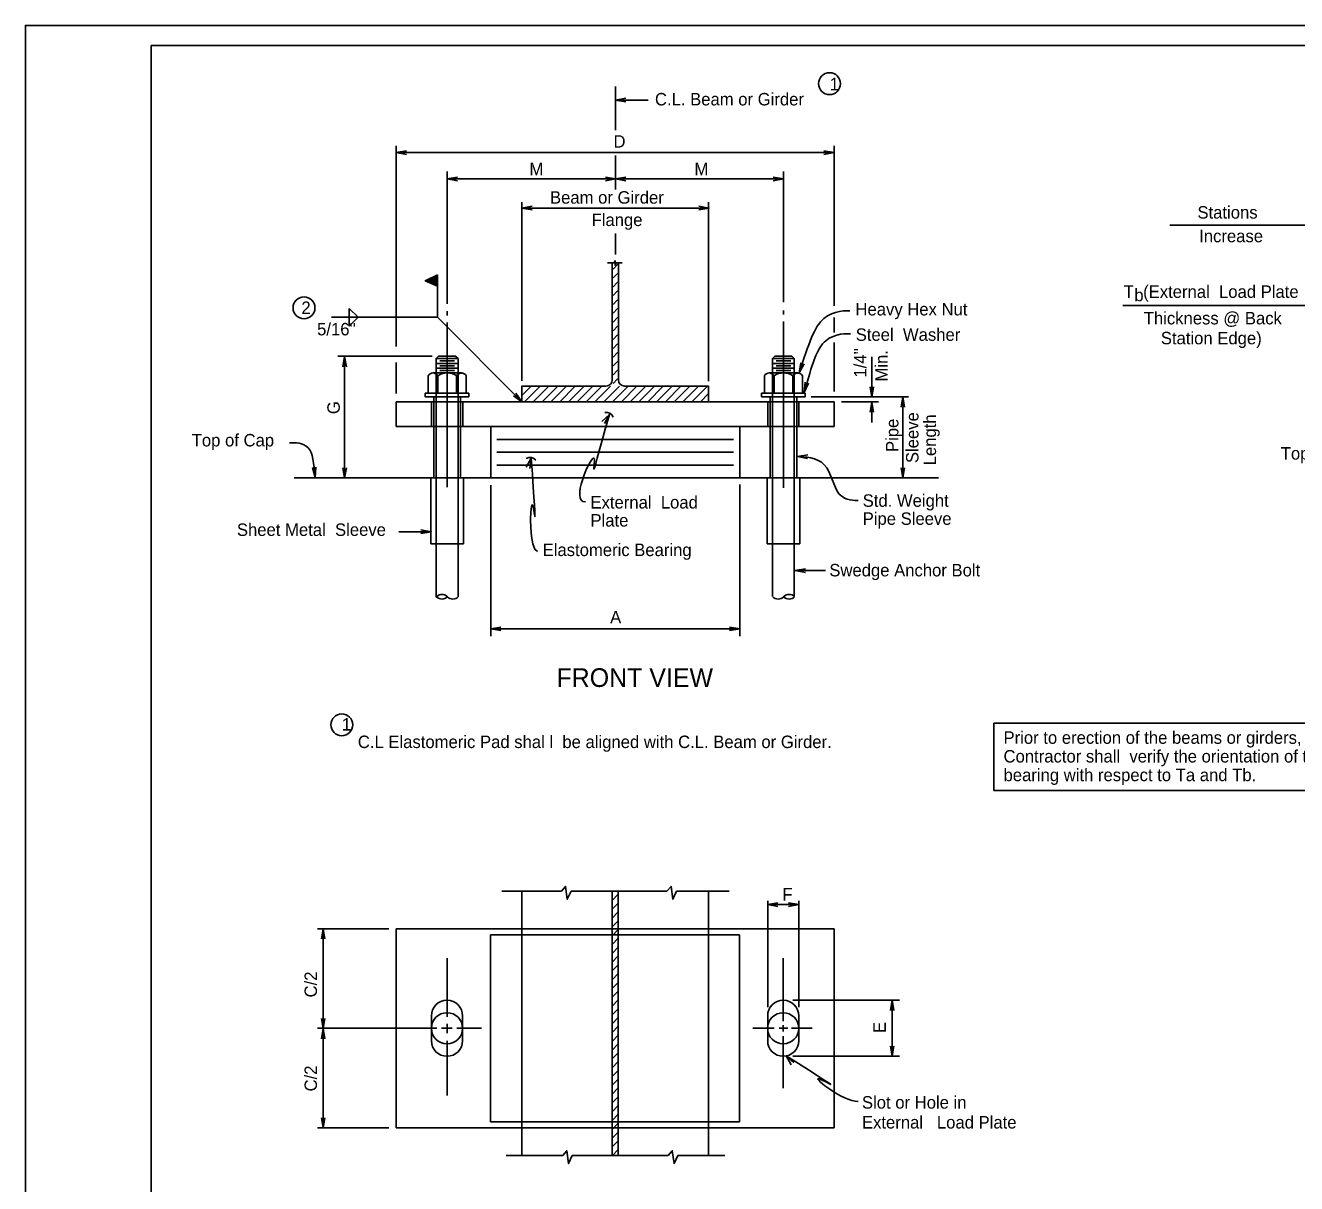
# Model space of a CAD drawing. Extents: x 32334 to 32601, y -901 to -733.
# Drawn here: x 32334.2 to 32436.3, y -826 to -733 of the extents above; entities that cross this region are included whole.
import ezdxf

# ---------------------------------------------------------------- set-up
doc = ezdxf.new("R2010")
doc.units = 0
for name, color, linetype in [('1', 7, 'Continuous'), ('B_Dimension', 7, 'Continuous'), ('Level 1', 7, 'Continuous'), ('Level 63', 7, 'Continuous')]:
    doc.layers.add(name, color=color, linetype=linetype)

msp = doc.modelspace()

# ---------------------------------------------------------------- linework, layer by layer
at = {"layer": '1'}
for p, q in [((32381.6, -741.38), (32381.6, -737.87)), ((32381.6, -738.97), (32384.21, -738.97)), ((32363.99, -758.76), (32363.99, -742.65)), ((32399.15, -755.49), (32399.15, -742.65)), ((32363.99, -743.19), (32399.15, -743.19)), ((32381.6, -746.15), (32381.6, -743.43)), ((32368.07, -755.33), (32368.07, -744.72)), ((32395.07, -755.2), (32395.07, -744.71)), ((32368.07, -745.31), (32381.6, -745.31)), ((32381.6, -745.31), (32395.07, -745.31)), ((32374.07, -761.51), (32374.07, -747.17)), ((32389.07, -761.54), (32389.07, -747.17)), ((32374.07, -747.64), (32389.09, -747.64)), ((32426.1, -749.02), (32438.8, -749.02)), ((32381.6, -751.38), (32381.6, -749.7)), ((32380.95, -752.04), (32381.48, -752.04)), ((32381.32, -752.04), (32381.32, -761.45)), ((32381.48, -752.04), (32381.57, -751.87)), ((32381.57, -751.87), (32381.57, -752.26)), ((32381.57, -752.26), (32381.64, -752.04)), ((32381.64, -752.04), (32382.13, -752.04)), ((32381.82, -761.45), (32381.82, -752.04)), ((32367.29, -753.02), (32366.31, -753.48)), ((32367.29, -753.93), (32367.29, -753.02)), ((32367.29, -753.02), (32367.29, -753.02)), ((32366.31, -753.48), (32367.29, -753.93)), ((32367.29, -753.93), (32367.29, -754.3)), ((32367.29, -754.3), (32367.29, -756.41)), ((32360.21, -757.12), (32360.21, -755.7)), ((32360.21, -755.7), (32360.92, -756.41)), ((32368.07, -756.27), (32368.07, -755.94)), ((32395.07, -756.19), (32395.07, -755.86)), ((32422.32, -755.47), (32439.1, -755.47)), ((32367.29, -756.41), (32358.78, -756.41)), ((32360.92, -756.41), (32360.21, -757.12)), ((32374.07, -763.2), (32367.29, -756.41)), ((32368.07, -770.06), (32368.07, -756.84)), ((32395.07, -770.12), (32395.07, -756.75)), ((32399.15, -757.63), (32399.15, -756.43)), ((32399.15, -762.39), (32399.15, -758.45)), ((32366.87, -759.53), (32359.29, -759.53)), ((32359.84, -769.32), (32359.84, -759.58)), ((32363.99, -762.53), (32363.99, -760.06)), ((32367.39, -759.53), (32367.2, -759.73)), ((32367.2, -760.89), (32367.2, -759.73)), ((32367.2, -759.73), (32368.95, -759.73)), ((32367.2, -760.12), (32368.95, -760.12)), ((32367.39, -759.53), (32368.75, -759.53)), ((32367.49, -759.92), (32368.66, -759.92)), ((32367.49, -760.31), (32368.66, -760.31)), ((32368.75, -759.53), (32368.95, -759.73)), ((32368.95, -760.89), (32368.95, -759.73)), ((32394.2, -759.73), (32394.39, -759.53)), ((32394.2, -759.73), (32395.95, -759.73)), ((32394.2, -760.89), (32394.2, -759.73)), ((32394.2, -759.73), (32395.95, -759.73)), ((32394.2, -760.12), (32395.95, -760.12)), ((32394.39, -759.53), (32395.75, -759.53)), ((32394.49, -759.92), (32395.66, -759.92)), ((32394.49, -760.31), (32395.66, -760.31)), ((32395.75, -759.53), (32395.95, -759.73)), ((32395.95, -760.89), (32395.95, -759.73)), ((32402.17, -762.83), (32402.17, -759.6)), ((32366.55, -762.5), (32366.55, -761.11)), ((32366.93, -760.89), (32369.22, -760.89)), ((32367.2, -760.51), (32368.95, -760.51)), ((32367.2, -769.32), (32367.2, -760.89)), ((32367.32, -762.5), (32367.32, -761.11)), ((32367.49, -760.7), (32368.66, -760.7)), ((32368.83, -762.5), (32368.83, -761.11)), ((32368.95, -769.32), (32368.95, -760.89)), ((32369.61, -762.5), (32369.61, -761.11)), ((32393.55, -762.5), (32393.55, -761.11)), ((32393.93, -760.89), (32396.22, -760.89)), ((32394.2, -760.51), (32395.95, -760.51)), ((32394.2, -769.32), (32394.2, -760.89)), ((32394.32, -762.5), (32394.32, -761.11)), ((32394.49, -760.7), (32395.66, -760.7)), ((32395.83, -762.5), (32395.83, -761.11)), ((32395.95, -769.32), (32395.95, -760.89)), ((32396.61, -762.5), (32396.61, -761.11)), ((32380.82, -761.95), (32374.07, -761.95)), ((32374.07, -761.95), (32374.07, -763.2)), ((32389.07, -761.95), (32382.32, -761.95)), ((32389.07, -763.2), (32389.07, -761.95)), ((32363.99, -765.2), (32363.99, -763.2)), ((32363.99, -763.2), (32399.15, -763.2)), ((32366.32, -762.5), (32369.82, -762.5)), ((32366.32, -762.5), (32366.32, -762.81)), ((32366.32, -762.81), (32369.82, -762.81)), ((32366.82, -765.2), (32366.82, -763.21)), ((32367.01, -763.21), (32367.01, -762.82)), ((32367.01, -765.2), (32367.01, -763.21)), ((32369.14, -763.21), (32369.14, -762.82)), ((32369.14, -765.2), (32369.14, -763.21)), ((32369.32, -765.2), (32369.32, -763.21)), ((32369.82, -762.5), (32369.82, -762.81)), ((32393.32, -762.5), (32396.82, -762.5)), ((32393.32, -762.5), (32393.32, -762.81)), ((32393.32, -762.81), (32396.82, -762.81)), ((32393.82, -765.21), (32393.82, -763.21)), ((32394.01, -763.21), (32394.01, -762.81)), ((32394.01, -765.21), (32394.01, -763.21)), ((32396.14, -763.21), (32396.14, -762.82)), ((32396.14, -765.22), (32396.14, -763.24)), ((32396.32, -765.22), (32396.32, -763.24)), ((32396.82, -762.5), (32396.82, -762.81)), ((32397.3, -762.81), (32405.12, -762.81)), ((32399.15, -765.2), (32399.15, -763.2)), ((32399.73, -763.2), (32402.72, -763.2)), ((32402.17, -764.88), (32402.17, -763.23)), ((32404.66, -769.32), (32404.66, -762.81)), ((32363.99, -765.2), (32399.15, -765.2)), ((32367.01, -769.32), (32367.01, -765.2)), ((32369.14, -769.32), (32369.14, -765.2)), ((32371.57, -765.2), (32371.57, -769.32)), ((32391.57, -765.2), (32391.57, -769.32)), ((32394.01, -769.32), (32394.01, -765.21)), ((32396.14, -769.32), (32396.14, -765.22)), ((32372.07, -766.23), (32391.07, -766.23)), ((32372.07, -767.26), (32391.07, -767.26)), ((32372.07, -768.29), (32391.07, -768.29)), ((32355.78, -769.32), (32407.54, -769.32)), ((32366.77, -774.61), (32366.77, -769.32)), ((32367.2, -769.32), (32367.2, -774.61)), ((32368.95, -769.32), (32368.95, -774.61)), ((32369.38, -774.61), (32369.38, -769.32)), ((32393.77, -774.61), (32393.77, -769.32)), ((32394.2, -769.32), (32394.2, -774.61)), ((32395.95, -769.32), (32395.95, -774.61)), ((32396.38, -774.61), (32396.38, -769.32)), ((32371.57, -769.89), (32371.57, -782.02)), ((32391.57, -769.84), (32391.57, -782.02)), ((32364.2, -773.64), (32366.79, -773.64)), ((32369.38, -774.61), (32366.77, -774.61)), ((32367.2, -774.61), (32367.2, -778.89)), ((32368.95, -774.61), (32368.95, -778.88)), ((32396.38, -774.61), (32393.77, -774.61)), ((32394.2, -774.61), (32394.2, -778.84)), ((32395.95, -774.61), (32395.95, -778.85)), ((32396.03, -776.76), (32398.46, -776.76)), ((32371.57, -781.45), (32391.57, -781.45)), ((32372.46, -802.52), (32377.25, -802.52)), ((32374.06, -823.75), (32374.06, -802.52)), ((32378.03, -802.52), (32385.72, -802.52)), ((32381.31, -823.75), (32381.31, -802.52)), ((32381.81, -802.52), (32381.81, -823.75)), ((32386.5, -802.52), (32390.71, -802.52)), ((32389.06, -823.75), (32389.06, -802.52)), ((32393.81, -811.83), (32393.81, -803.28)), ((32396.31, -811.83), (32396.31, -803.28)), ((32393.81, -803.59), (32396.31, -803.59)), ((32363.4, -805.53), (32357.67, -805.53)), ((32358.12, -805.53), (32358.12, -813.55)), ((32363.98, -805.53), (32363.98, -821.53)), ((32363.98, -805.53), (32374.03, -805.53)), ((32371.56, -806.03), (32371.56, -821.03)), ((32371.56, -806.03), (32391.56, -806.03)), ((32374.03, -805.53), (32389.09, -805.53)), ((32389.09, -805.53), (32399.14, -805.53)), ((32391.56, -806.03), (32391.56, -821.03)), ((32399.14, -805.53), (32399.14, -821.53)), ((32368.06, -812.62), (32368.06, -807.89)), ((32395.06, -812.96), (32395.06, -807.89)), ((32395.82, -811.28), (32404.39, -811.28)), ((32403.8, -811.28), (32403.8, -815.78)), ((32357.67, -813.53), (32367.25, -813.53)), ((32366.81, -814.53), (32366.81, -812.53)), ((32367.63, -813.53), (32368.48, -813.53)), ((32368.06, -813.93), (32368.06, -813.17)), ((32368.86, -813.53), (32369.31, -813.53)), ((32369.31, -814.53), (32369.31, -812.53)), ((32369.31, -813.53), (32370.83, -813.53)), ((32392.61, -813.53), (32394.34, -813.53)), ((32393.81, -814.53), (32393.81, -812.53)), ((32394.72, -813.53), (32395.43, -813.53)), ((32395.06, -813.79), (32395.06, -813.29)), ((32395.72, -813.53), (32396.31, -813.53)), ((32396.31, -814.53), (32396.31, -812.53)), ((32396.31, -813.53), (32397.39, -813.53)), ((32358.12, -813.55), (32358.12, -821.53)), ((32368.06, -818.93), (32368.06, -814.54)), ((32395.06, -818.34), (32395.06, -814.15)), ((32395.82, -815.78), (32404.39, -815.78)), ((32363.4, -821.53), (32357.67, -821.53)), ((32363.98, -821.53), (32374.03, -821.53)), ((32371.56, -821.03), (32391.56, -821.03)), ((32374.03, -821.53), (32389.04, -821.53)), ((32389.04, -821.53), (32399.14, -821.53)), ((32372.8, -823.75), (32377.35, -823.75)), ((32378.12, -823.75), (32385.82, -823.75)), ((32386.6, -823.75), (32390.37, -823.75))]:
    msp.add_line(p, q, dxfattribs=at)
for points in [[(32381.39, -752.56), (32381.76, -752.18)], [(32366.69, -753.65), (32366.69, -753.3)], [(32366.74, -753.67), (32366.74, -753.28)], [(32366.79, -753.7), (32366.79, -753.26)], [(32366.84, -753.72), (32366.84, -753.23)], [(32366.89, -753.75), (32366.89, -753.21)], [(32366.95, -753.77), (32366.95, -753.18)], [(32367, -753.79), (32367, -753.16)], [(32367.05, -753.82), (32367.05, -753.14)], [(32367.1, -753.84), (32367.1, -753.11)], [(32367.15, -753.87), (32367.15, -753.09)], [(32367.2, -753.89), (32367.2, -753.06)], [(32367.26, -753.91), (32367.26, -753.04)], [(32381.39, -753.26), (32381.76, -752.89)], [(32366.33, -753.48), (32366.33, -753.47)], [(32366.38, -753.51), (32366.38, -753.45)], [(32366.43, -753.53), (32366.43, -753.42)], [(32366.48, -753.55), (32366.48, -753.4)], [(32366.53, -753.58), (32366.53, -753.38)], [(32366.58, -753.6), (32366.58, -753.35)], [(32366.64, -753.63), (32366.64, -753.33)], [(32381.39, -753.97), (32381.76, -753.6)], [(32381.39, -754.68), (32381.76, -754.3)], [(32381.39, -755.39), (32381.76, -755.01)], [(32381.39, -756.09), (32381.76, -755.72)], [(32381.39, -756.8), (32381.76, -756.43)], [(32381.39, -757.51), (32381.76, -757.13)], [(32381.39, -758.21), (32381.76, -757.84)], [(32381.39, -758.92), (32381.76, -758.55)], [(32381.39, -759.63), (32381.76, -759.25)], [(32381.39, -760.33), (32381.76, -759.96)], [(32381.39, -761.04), (32381.76, -760.67)], [(32381.39, -761.75), (32381.76, -761.37)], [(32374.07, -762.7), (32374.82, -761.95)], [(32374.07, -761.99), (32374.12, -761.95)], [(32374.28, -763.2), (32375.53, -761.95)], [(32374.99, -763.2), (32376.24, -761.95)], [(32375.7, -763.2), (32376.95, -761.95)], [(32376.4, -763.2), (32377.65, -761.95)], [(32377.11, -763.2), (32378.36, -761.95)], [(32377.82, -763.2), (32379.07, -761.95)], [(32378.52, -763.2), (32379.77, -761.95)], [(32379.23, -763.2), (32380.48, -761.95)], [(32379.94, -763.2), (32381.19, -761.95)], [(32380.65, -763.2), (32381.9, -761.95)], [(32381.35, -763.2), (32382.6, -761.95)], [(32382.06, -763.2), (32383.31, -761.95)], [(32382.77, -763.2), (32384.02, -761.95)], [(32383.47, -763.2), (32384.72, -761.95)], [(32384.18, -763.2), (32385.43, -761.95)], [(32384.89, -763.2), (32386.14, -761.95)], [(32385.6, -763.2), (32386.84, -761.95)], [(32386.3, -763.2), (32387.55, -761.95)], [(32387.01, -763.2), (32388.26, -761.95)], [(32387.72, -763.2), (32388.97, -761.95)], [(32368.2, -763.2), (32368.2, -763.2)], [(32369.62, -763.2), (32369.62, -763.2)], [(32370.32, -763.2), (32370.32, -763.2)], [(32388.42, -763.2), (32389.07, -762.55)], [(32393.79, -763.2), (32393.79, -763.2)], [(32377.25, -802.52), (32377.58, -802.13), (32377.72, -803.17), (32378.03, -802.52)], [(32385.72, -802.52), (32386.05, -802.13), (32386.2, -803.17), (32386.5, -802.52)], [(32381.31, -803.26), (32381.81, -802.76)], [(32381.31, -803.97), (32381.81, -803.47)], [(32381.31, -804.68), (32381.81, -804.18)], [(32381.31, -805.39), (32381.81, -804.89)], [(32381.31, -806.09), (32381.81, -805.59)], [(32381.31, -806.8), (32381.81, -806.3)], [(32381.31, -807.51), (32381.81, -807.01)], [(32381.31, -808.21), (32381.81, -807.71)], [(32381.31, -808.92), (32381.81, -808.42)], [(32381.31, -809.63), (32381.81, -809.13)], [(32381.31, -810.33), (32381.81, -809.84)], [(32381.31, -811.04), (32381.81, -810.54)], [(32381.31, -811.75), (32381.81, -811.25)], [(32381.31, -812.46), (32381.81, -811.96)], [(32381.31, -813.16), (32381.81, -812.66)], [(32381.31, -813.87), (32381.81, -813.37)], [(32381.31, -814.58), (32381.81, -814.08)], [(32381.31, -815.28), (32381.81, -814.79)], [(32381.31, -815.99), (32381.81, -815.49)], [(32381.31, -816.7), (32381.81, -816.2)], [(32381.31, -817.41), (32381.81, -816.91)], [(32381.31, -818.11), (32381.81, -817.61)], [(32381.31, -818.82), (32381.81, -818.32)], [(32381.31, -819.53), (32381.81, -819.03)], [(32381.31, -820.23), (32381.81, -819.74)], [(32381.31, -820.94), (32381.81, -820.44)], [(32381.31, -821.65), (32381.81, -821.15)], [(32381.31, -822.36), (32381.81, -821.86)], [(32381.31, -823.06), (32381.81, -822.56)], [(32377.35, -823.75), (32377.68, -823.36), (32377.82, -824.4), (32378.12, -823.75)], [(32381.31, -823.77), (32381.81, -823.27)], [(32385.82, -823.75), (32386.15, -823.36), (32386.29, -824.4), (32386.6, -823.75)]]:
    msp.add_lwpolyline(points, dxfattribs=at)
msp.add_lwpolyline([(32411.97, -789.01), (32447.26, -789.01), (32447.26, -794.42), (32411.97, -794.42)], close=True, dxfattribs=at)
for centre, radius in [((32398.78, -737.65), 0.88), ((32356.58, -755.66), 0.88), ((32359.61, -789.15), 0.88), ((32368.06, -813.53), 1.25), ((32395.06, -813.53), 1.25)]:
    msp.add_circle(centre, radius, dxfattribs=at)
for centre, radius, start, end in [((32366.93, -761.34), 0.45, 30.8086, 149.1914), ((32368.08, -762.31), 1.42, 57.6898, 122.3102), ((32369.22, -761.35), 0.452, 30.9573, 149.0427), ((32380.83, -761.45), 0.5, 270, 360), ((32382.32, -761.45), 0.5, 180, 270), ((32393.93, -761.34), 0.45, 30.8086, 149.1914), ((32395.08, -762.31), 1.42, 57.6898, 122.3102), ((32396.22, -761.35), 0.452, 30.9573, 149.0427), ((32380.84, -764.66), 0.615, 21.6992, 99.9226), ((32374.72, -768.29), 0.615, 40.3962, 118.6196), ((32367.66, -779.28), 0.605, 43.7135, 136.2865), ((32395.53, -779.28), 0.605, 43.7135, 136.2865), ((32367.66, -778.45), 0.605, 223.7135, 316.2865), ((32368.53, -778.45), 0.605, 223.7135, 316.2865), ((32394.66, -778.45), 0.605, 223.7135, 316.2865), ((32395.53, -778.45), 0.605, 223.7135, 316.2865), ((32368.06, -812.53), 1.25, 0, 180), ((32395.06, -812.53), 1.25, 0, 180), ((32368.06, -814.53), 1.25, 180, 0), ((32395.06, -814.53), 1.25, 180, 0)]:
    msp.add_arc(centre, radius, start, end, dxfattribs=at)
for points in [[(32400.41, -755.89), (32400.21, -755.88), (32397.97, -755.85), (32397.12, -758.49), (32396.34, -760.89)], [(32400.45, -757.74), (32400.25, -757.73), (32398.13, -757.65), (32397.39, -760.16), (32396.74, -762.46)], [(32379.17, -771.25), (32377.95, -771.25), (32381.1, -764.22), (32379.17, -771.25), (32381.1, -764.22)], [(32355.42, -766.51), (32355.84, -766.48), (32357.21, -766.49), (32357.37, -768.12), (32357.47, -769.28)], [(32401.07, -771.13), (32400.87, -771.14), (32399.22, -771.22), (32398.8, -767.7), (32396.75, -767.62), (32396.21, -767.59)], [(32375.33, -775.23), (32374.63, -775.19), (32374.83, -767.74), (32375.33, -775.23), (32374.83, -767.74)], [(32401.09, -819.42), (32399.8, -819.38), (32395.3, -815.74), (32401.09, -819.42), (32395.3, -815.74)]]:
    msp.add_open_spline(points, degree=3, dxfattribs=at)
at = {"layer": 'B_Dimension'}
for points in [[(32382.42, -739.11), (32381.6, -738.97), (32382.42, -738.82)], [(32364.81, -743.33), (32363.99, -743.19), (32364.81, -743.04)], [(32398.33, -743.04), (32399.15, -743.19), (32398.33, -743.33)], [(32368.89, -745.45), (32368.07, -745.31), (32368.89, -745.16)], [(32380.78, -745.16), (32381.6, -745.31), (32380.78, -745.45)], [(32382.42, -745.45), (32381.6, -745.31), (32382.42, -745.16)], [(32394.25, -745.16), (32395.07, -745.31), (32394.25, -745.45)], [(32374.89, -747.79), (32374.07, -747.64), (32374.89, -747.5)], [(32388.27, -747.5), (32389.09, -747.64), (32388.27, -747.79)], [(32359.7, -760.4), (32359.84, -759.58), (32359.99, -760.4)], [(32396.73, -760.16), (32396.34, -760.89), (32396.46, -760.07)], [(32397.1, -761.71), (32396.74, -762.46), (32396.83, -761.63)], [(32402.31, -762.01), (32402.17, -762.83), (32402.03, -762.01)], [(32373.6, -762.52), (32374.07, -763.2), (32373.39, -762.72)], [(32402.03, -764.05), (32402.17, -763.23), (32402.31, -764.05)], [(32404.52, -763.63), (32404.66, -762.81), (32404.81, -763.63)], [(32380.48, -764.78), (32381.1, -764.22), (32380.71, -764.96)], [(32397.02, -767.77), (32396.21, -767.59), (32397.03, -767.48)], [(32357.54, -768.45), (32357.47, -769.28), (32357.25, -768.48)], [(32359.99, -768.5), (32359.84, -769.32), (32359.7, -768.5)], [(32374.42, -768.47), (32374.83, -767.74), (32374.7, -768.56)], [(32404.81, -768.5), (32404.66, -769.32), (32404.52, -768.5)], [(32365.97, -773.49), (32366.79, -773.64), (32365.97, -773.78)], [(32396.85, -776.91), (32396.03, -776.76), (32396.85, -776.62)], [(32372.39, -781.59), (32371.57, -781.45), (32372.39, -781.3)], [(32390.75, -781.3), (32391.57, -781.45), (32390.75, -781.59)], [(32394.63, -803.74), (32393.81, -803.59), (32394.63, -803.45)], [(32395.49, -803.45), (32396.31, -803.59), (32395.49, -803.74)], [(32357.98, -806.35), (32358.12, -805.53), (32358.26, -806.35)], [(32403.66, -812.1), (32403.8, -811.28), (32403.95, -812.1)], [(32358.26, -812.73), (32358.12, -813.55), (32357.98, -812.73)], [(32357.98, -814.37), (32358.12, -813.55), (32358.26, -814.37)], [(32403.95, -814.96), (32403.8, -815.78), (32403.66, -814.96)], [(32395.69, -816.47), (32395.3, -815.74), (32395.92, -816.29)], [(32358.26, -820.71), (32358.12, -821.53), (32357.98, -820.71)]]:
    msp.add_lwpolyline(points, dxfattribs=at)
at = {"layer": 'Level 1'}
for p, q in [((32344.3, -734.59), (32597.25, -734.59)), ((32344.3, -898.95), (32344.3, -734.59))]:
    msp.add_line(p, q, dxfattribs=at)
at = {"layer": 'Level 63'}
msp.add_lwpolyline([(32334.21, -900.55), (32600.85, -900.55), (32600.85, -732.97), (32334.21, -732.97)], close=True, dxfattribs=at)

# ---------------------------------------------------------------- texts
at = {"layer": '1'}
for s, height, p in [('1', 1, (32398.79, -738.18)), ('C.L. Beam or Girder', 1, (32384.76, -739.4)), ('D', 1, (32381.43, -742.79)), ('M', 1, (32374.68, -745.01)), ('M', 1, (32387.93, -745.01)), ('Beam or Girder', 1, (32376.33, -747.29)), ('Flange', 1, (32379.67, -749.09)), ('Stations', 1, (32428.32, -748.49)), ('Increase', 1, (32428.46, -750.39)), ('T  (External  Load Plate', 1, (32422.4, -754.86)), ('b', 1, (32423.25, -755.13)), ('2', 1, (32356.37, -756.15)), ('Heavy Hex Nut', 1, (32400.86, -756.27)), ('Thickness @ Back', 1, (32424.01, -756.99)), ("5/16''", 1, (32357.63, -757.87)), ('Steel  Washer', 1, (32400.88, -758.31)), ('Station Edge)', 1, (32425.38, -758.59)), ('Top of Cap', 1, (32347.56, -766.79)), ('Top of Cap', 1, (32435.01, -767.85)), ('Std. Weight ', 1, (32401.44, -771.64)), ('External  Load ', 1, (32379.58, -771.78)), ('Plate', 1, (32379.58, -773.23)), ('Pipe Sleeve', 1, (32401.44, -773.09)), ('Sheet Metal  Sleeve', 1, (32351.19, -773.98)), ('Elastomeric Bearing', 1, (32375.74, -775.6)), ('Swedge Anchor Bolt', 1, (32398.76, -777.23)), ('A', 1, (32381.16, -781)), ('FRONT VIEW', 1.498, (32376.85, -786.11)), ('1', 1, (32359.62, -789.61)), ('C.L Elastomeric Pad shal l  be aligned with C.L. Beam or Girder.', 1, (32360.9, -791.02)), ('Prior to erection of the beams or girders, the ', 1, (32412.75, -790.68)), ('Contractor shall  verify the orientation of the ', 1, (32412.75, -792.18)), ('bearing with respect to Ta and Tb.', 1, (32412.75, -793.68)), ('F', 1, (32394.99, -803.27)), ('Slot or Hole in', 1, (32401.38, -819.98)), ('External   Load Plate', 1, (32401.38, -821.58))]:
    msp.add_text(s, height=height, dxfattribs=at).set_placement(p)
for s, p in [("1/4''", (32401.74, -761.26)), ('Min.', (32403.45, -761.58)), ('G', (32359.45, -764.2)), ('Sleeve ', (32405.92, -768.13)), ('Length', (32407.33, -768.31)), ('Pipe', (32404.31, -767.24)), ('C/2', (32357.62, -811.05)), ('E', (32403.3, -813.91)), ('C/2', (32357.62, -818.6))]:
    msp.add_text(s, height=1, rotation=90, dxfattribs=at).set_placement(p)

doc.saveas('drawing.dxf')
